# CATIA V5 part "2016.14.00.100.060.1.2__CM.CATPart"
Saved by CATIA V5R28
Part number: 2016.14.00.100.060.1.2__CM
Property "id_number": "2016.14.00.100.060.1.2"
Publications: "Absolute Axis System", "driver", "slider", "base", "cam diagram"
Bounding box of the stored display mesh (mm): x -60 to 210, y -87.5 to 87.5, z 0 to 260
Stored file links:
  N:\B2\Normteile\K\2016\11-14\010\cm\2016.14.00.100.060.1.2__CM.CATPart
  H:\CAD_Startmodelle\Tests\fill-in_PRT-SL_TEMPLATE.xlsx
  H:\CAD_Startmodelle\V5-R24\R24_TEMPLATE_PRT_FIBRO_CAM_TECNOLOGIES_INDEX.xlsx
  H:\z_Einordnen\170511__Anfrage_TK_HN\170511__CC01_TKHN.CATPart
  N:\B2\Normteile\K\2016\9xxx\2016.9024.1705.001\Entwurf_\170511__CC01_TKHN.CATPart
  N:\B2\Normteile\K\2016\9xxx\2016.9024.1707.006\Konstruktion\2016.9024.1707.006__HP__CUSTOMIZED_CAM_CM.CATPart
  N:\B2\Normteile\K\2016\9xxx\2016.9024.1707.005\Konstruktion\2016.9024.1707.005__HP__CUSTOMIZED_CAM_CM.CATPart
  N:\B2\Normteile\K\2016\9xxx\2016.9024.1707.008\Konstruktion\2016.9024.1707.008__HP__CUSTOMIZED_CAM_CM.CATPart
  N:\B2\Normteile\K\2016\9xxx\2016.9024.1707.009\Konstruktion\2016.9024.1707.009__HP__CUSTOMIZED_CAM_CM.CATPart
  N:\B2\Normteile\K\2016\9xxx\2016.9024.1707.010\Konstruktion\2016.9024.1707.010__HP__CUSTOMIZED_CAM_CM.CATPart
  N:\B2\Normteile\K\2016\9xxx\2016.9024.1708.002\Konstruktion\2016.9024.1708.002__HP__CUSTOMIZED_CAM_CM.CATPart
  N:\B2\Normteile\K\2016\9xxx\2016.9024.1802.001\Konstruktion\2016.9024.1802.001__HP__CUSTOMIZED_CAM_CM.CATPart
  N:\B2\Normteile\K\2016\9xxx\2016.9024.1802.002\Konstruktion\2016.9024.1802.002__HP__CUSTOMIZED_CAM_CM.CATPart
  N:\B2\Normteile\K\2016\9xxx\2016.9024.1811.003\Konstruktion\2016.9024.1811.003__HP__CUSTOMIZED_CAM_CM.CATPart
  N:\B2\Normteile\K\2016\9xxx\2016.9015.1811.001\Konstruktion\am\2016.9015.1811.001__AM__FCC_HV_DMC_0125-00.CATPart
  N:\B2\Normteile\K\2016\9xxx\2016.9024.1811.009\Konstruktion\2016.9024.1811.009__HP__CUSTOMIZED_CAM_CM.CATPart
  N:\B2\Normteile\K\2016\9xxx\2016.9024.1911.002\Konstruktion\am\2016.9024.1911.002__AM__CUSTOMIZED_CAM_CM.CATPart
  N:\B2\Normteile\K\2016\9xxx\2016.9024.2002.006\Konstruktion\2016.9024.2002.006__AM.CATPart
  N:\B2\Normteile\K\2016\9xxx\2016.9024.2004.001\Konstruktion\2016.9024.2004.001__AM__FCC_HV_CAEC_0260-45.CATPart
  N:\B2\Normteile\K\2016\9xxx\2016.9024.2006.002\Konstruktion\2016.9024.2006.002__AM__FCC_HV_CAEC_0260-40.CATPart
  N:\B2\Normteile\K\2016\9xxx\2016.9024.2006.005\Konstruktion\am\2016.9024.2006.005__AM__CFCC_HV_AEPC_0080-65.CATPart
  N:\B2\Normteile\K\2016\9xxx\2016.9024.2006.004\Konstruktion\am\2016.9024.2006.004__AM__CFCC_HV_AEC_0210-35.CATPart
  N:\B2\Normteile\K\2016\9xxx\2016.9026.2006.001\Konstruktion\am\2016.9026.2006.001__AM__FCC_LV_CAEC_0180-40.CATPart
  N:\B2\Normteile\K\2016\9xxx\2016.9015.2007.001\Konstruktion\am\2016.9015.2007.001__AM__FCC_HV_CDMPC_0090-00.CATPart
  N:\B2\Normteile\K\2016\9xxx\2016.9024.2005.001\Konstruktion\am\2016.9024.2005.001__AM__CFCC_HV_AEPC_1400-70.CATPart
  N:\B2\Normteile\K\2016\9xxx\2016.9024.2007.004\Konstruktion\am\2016.9024.2007.004__AM__CFCC_HV_AEC_1250-80.CATPart
  N:\B2\Normteile\K\2016\11-14\005\2016.11.00.052.040.1.02__AS__DIE_MOUNT_CAM__W52_A0_S40.CATProduct
  N:\B2\Normteile\K\2016\11-14\cm\005\catia\2016.11.00.052.025.1.2__CM.CATPart
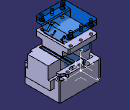
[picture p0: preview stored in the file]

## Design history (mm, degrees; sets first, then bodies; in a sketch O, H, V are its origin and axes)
Parameters
  group "process_parameters"
    modeltype = ""
    stocklist = ""
    id_number = "2016.14.00.100.060.1.2"
    id_number_rough_part = ""
    revision_index = ""
    revision_date = ""
    revision_description = ""
    category = ""
    material = ""
    manufacturing_information = ""
    standard = ""
  group "release_parameters_startmodel"
    sm_revision_index = "2016_00" {design table}
    sm_revision_date = "20.08.2016" {design table}
    sm_revision_name = "Meyer" {design table}
    sm_revision_description = "new part template FIBRO cam tecnologies" {design table}
AxisSystem1: origin (0, 0, 0), X (1, 0, 0), Y (0, 1, 0), Z (0, 0, 1)
Set1 "reference elements"
  Sketch1 "cam diagram" on ZX plane of AxisSystem1, origin (0, 0, 0), H (-1, 0, 0), V (0, 0, 1)
    line L1 (0, 0) -> (60, 0)
    line L2 (60, 0) -> (0, 60)
    point P2 (0, 60)
    line L3 (0, 60) -> (0, 0)
    length L1 = 60
    angle H L2 = 45
    horizontal: L1 H
    coincidence: P2 V
    vertical: L3 V
Body1 "finished_part" (main body)
  Body2 "rough_part"
  Add1 "rough_part": tool Body2
  Body3 "milling operations"
  Remove1 "milling operations": tool Body3
  Body4 "drilling operations"
  Remove2 "drilling operations": tool Body4
Body5 "driver"
  Solid1: solid without history
Body6 "slider"
  Solid2: solid without history
Body7 "base"
  Solid3: solid without history
Body8 "opened position"
  Body9 "slider"
    Body10 "slider"
      Solid4: linked copy from another document
    Assemble1: tool Body10
    Translate1: FirstPoint vertex [element of Sketch1 | element of Sketch1], SecondPoint vertex [element of Sketch1 | element of Sketch1], ToTransfor Assemble1
  Assemble2: tool Body9
  Body11 "driver"
    Body12 "driver"
      Solid5: linked copy from another document
    Assemble3: tool Body12
    Translate2: FirstPoint vertex [element of Sketch1 | element of Sketch1], SecondPoint vertex [element of Sketch1 | element of Sketch1], ToTransfor Assemble3
  Assemble4: tool Body11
